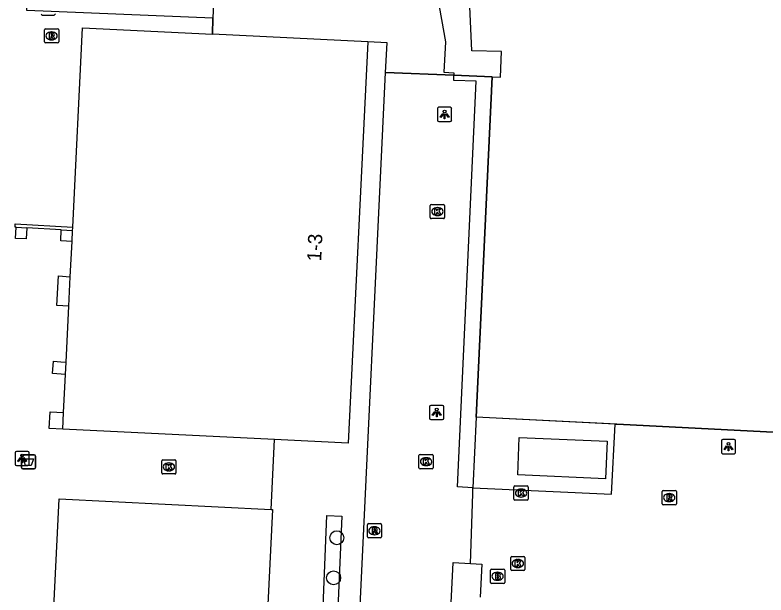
# Model space of a CAD drawing. Extents: x 161761 to 162722, y 384793 to 385405.
# Drawn here: x 162373.4 to 162426.2, y 385061.7 to 385102.4 of the extents above; entities that cross this region are included whole.
import ezdxf

# ---------------------------------------------------------------- set-up
doc = ezdxf.new("R2010")
doc.units = 0
for name, color, linetype in [('IMGEO_Afvalbak', 7, 'Continuous'), ('IMGEO_Boom', 7, 'Continuous'), ('IMGEO_Brandkraan', 7, 'Continuous'), ('IMGEO_Groenvoorziening', 7, 'Continuous'), ('IMGEO_Haag', 7, 'Continuous'), ('IMGEO_Hek', 7, 'Continuous'), ('IMGEO_Kolk', 7, 'Continuous'), ('IMGEO_Lichtpunt', 7, 'Continuous'), ('IMGEO_Loofbos', 7, 'Continuous'), ('IMGEO_Pand', 7, 'Continuous'), ('IMGEO_Pand_nummerreeks', 7, 'Continuous'), ('IMGEO_Rioolput', 7, 'Continuous'), ('IMGEO_Voetpad_open', 7, 'Continuous')]:
    doc.layers.add(name, color=color, linetype=linetype)

msp = doc.modelspace()

# ---------------------------------------------------------------- linework, layer by layer
at = {"layer": 'IMGEO_Afvalbak'}
for p, q in [((162373.853, 385070.657), (162373.853, 385071.457)), ((162373.853, 385071.457), (162373.853, 385070.657)), ((162373.953, 385071.557), (162374.743, 385071.557)), ((162374.743, 385071.557), (162373.953, 385071.557)), ((162374.843, 385071.457), (162374.843, 385070.657)), ((162374.843, 385070.657), (162374.843, 385071.457)), ((162374.743, 385070.557), (162373.953, 385070.557)), ((162373.953, 385070.557), (162374.743, 385070.557))]:
    msp.add_line(p, q, dxfattribs=at)
msp.add_lwpolyline([(162373.996, 385071.271), (162374.7, 385071.271), (162374.551, 385070.801), (162374.145, 385070.801), (162373.996, 385071.271)], dxfattribs=at)
for centre, start, end in [((162373.953, 385071.457), 90, 180), ((162373.953, 385071.457), 90, 180), ((162374.743, 385071.457), 0, 90), ((162374.743, 385071.457), 360, 90), ((162373.953, 385070.657), 180, 270), ((162373.953, 385070.657), 180, 270), ((162374.743, 385070.657), 270, 0), ((162374.743, 385070.657), 270, 0)]:
    msp.add_arc(centre, 0.1, start, end, dxfattribs=at)
at = {"layer": 'IMGEO_Boom'}
for centre in [(162396.02, 385065.722), (162395.798, 385062.901)]:
    msp.add_circle(centre, 0.489, dxfattribs=at)
at = {"layer": 'IMGEO_Brandkraan'}
for p, q in [((162406.822, 385062.587), (162406.822, 385063.439)), ((162406.897, 385063.513), (162407.749, 385063.513)), ((162407.31, 385063.293), (162407.335, 385063.293)), ((162407.823, 385063.439), (162407.823, 385062.587)), ((162407.333, 385062.733), (162407.308, 385062.733)), ((162407.749, 385062.513), (162406.897, 385062.513))]:
    msp.add_line(p, q, dxfattribs=at)
for points in [[(162406.822, 385062.587), (162406.822, 385063.439)], [(162406.897, 385063.513), (162407.749, 385063.513)], [(162407.823, 385063.439), (162407.823, 385062.587)], [(162407.17, 385063.213), (162407.17, 385062.813), (162407.383, 385062.813)], [(162407.401, 385063.213), (162407.17, 385063.213)], [(162407.349, 385063.132), (162407.295, 385063.132), (162407.295, 385063.056)], [(162407.295, 385063.056), (162407.348, 385063.056)], [(162407.357, 385062.98), (162407.295, 385062.98), (162407.295, 385062.899)], [(162407.295, 385062.899), (162407.357, 385062.899)], [(162407.749, 385062.513), (162406.897, 385062.513)]]:
    msp.add_lwpolyline(points, dxfattribs=at)
for centre, radius, start, end in [((162406.899, 385063.437), 0.0765, 91.552, 178.448), ((162406.899, 385063.437), 0.0765, 91.552, 178.448), ((162407.747, 385063.437), 0.0765, 1.552, 88.448), ((162407.747, 385063.437), 0.0765, 1.552, 88.448), ((162407.35, 385063.094), 0.0379, 267.8285, 90.9355), ((162407.358, 385062.939), 0.0404, 269.8759, 90.5077), ((162407.389, 385063.064), 0.251, 268.6676, 293.5347), ((162407.405, 385063.068), 0.145, 59.4692, 91.5367), ((162407.43, 385063.115), 0.0922, 285.5137, 58.1501), ((162407.435, 385062.923), 0.105, 301.3115, 78.989), ((162406.899, 385062.589), 0.0765, 181.552, 268.448), ((162406.899, 385062.589), 0.0765, 181.552, 268.448), ((162407.747, 385062.589), 0.0765, 271.552, 358.448), ((162407.747, 385062.589), 0.0765, 271.552, 358.448)]:
    msp.add_arc(centre, radius, start, end, dxfattribs=at)
for centre, major_axis, ratio, start_param, end_param in [((162407.309, 385063.013), (-0.387, 0.002), 0.722429, 4.712389, 7.853982), ((162407.334, 385063.013), (-0.39, 0.002), 0.717154, 1.570796, 4.712389)]:
    msp.add_ellipse(centre, major_axis=major_axis, ratio=ratio, start_param=start_param, end_param=end_param, dxfattribs=at)
at = {"layer": 'IMGEO_Groenvoorziening'}
for points in [[(162373.496, 385087.535), (162374.232, 385087.489)], [(162376.647, 385087.355), (162377.453, 385087.31)]]:
    msp.add_lwpolyline(points, dxfattribs=at)
at = {"layer": 'IMGEO_Haag'}
for points in [[(162406.946, 385098.102), (162407.536, 385098.075), (162407.59, 385099.872), (162405.506, 385099.92), (162405.19, 385107.198), (162407.287, 385109.447), (162408.471, 385113.399), (162408.538, 385116.438), (162406.588, 385116.444)], [(162404.247, 385098.213), (162406.946, 385098.102)], [(162406.946, 385098.102), (162405.822, 385074.201)], [(162405.414, 385063.918), (162406.21, 385063.87), (162406.102, 385061.54)]]:
    msp.add_lwpolyline(points, dxfattribs=at)
at = {"layer": 'IMGEO_Hek'}
for points in [[(162387.301, 385102.223), (162387.283, 385101.087)], [(162404.247, 385098.213), (162399.452, 385098.409)], [(162406.946, 385098.102), (162404.247, 385098.213)], [(162405.822, 385074.201), (162406.946, 385098.102)], [(162405.822, 385074.201), (162405.588, 385069.236)], [(162416.171, 385073.671), (162405.822, 385074.201)], [(162438.563, 385072.523), (162416.171, 385073.671)], [(162391.403, 385067.713), (162391.641, 385072.611)]]:
    msp.add_lwpolyline(points, dxfattribs=at)
at = {"layer": 'IMGEO_Kolk'}
for p, q in [((162402.668, 385089.134), (162403.52, 385089.134)), ((162402.593, 385088.208), (162402.593, 385089.06)), ((162403.081, 385088.914), (162403.106, 385088.914)), ((162403.594, 385089.06), (162403.594, 385088.208)), ((162403.52, 385088.134), (162402.668, 385088.134)), ((162403.104, 385088.354), (162403.079, 385088.354)), ((162383.794, 385071.2), (162384.646, 385071.2)), ((162401.799, 385070.64), (162401.799, 385071.492)), ((162401.874, 385071.566), (162402.726, 385071.566)), ((162402.287, 385071.346), (162402.312, 385071.346)), ((162402.8, 385071.492), (162402.8, 385070.64)), ((162383.719, 385070.274), (162383.719, 385071.126)), ((162384.207, 385070.98), (162384.232, 385070.98)), ((162384.72, 385071.126), (162384.72, 385070.274)), ((162402.31, 385070.786), (162402.285, 385070.786)), ((162384.646, 385070.2), (162383.794, 385070.2)), ((162384.23, 385070.42), (162384.205, 385070.42)), ((162402.726, 385070.566), (162401.874, 385070.566)), ((162408.471, 385068.432), (162408.471, 385069.284)), ((162408.546, 385069.358), (162409.398, 385069.358)), ((162408.959, 385069.138), (162408.984, 385069.138)), ((162409.472, 385069.284), (162409.472, 385068.432)), ((162408.982, 385068.578), (162408.957, 385068.578)), ((162409.398, 385068.358), (162408.546, 385068.358)), ((162408.245, 385063.487), (162408.245, 385064.339)), ((162408.32, 385064.413), (162409.172, 385064.413)), ((162409.246, 385064.339), (162409.246, 385063.487)), ((162408.733, 385064.193), (162408.758, 385064.193)), ((162409.172, 385063.413), (162408.32, 385063.413)), ((162408.756, 385063.633), (162408.731, 385063.633))]:
    msp.add_line(p, q, dxfattribs=at)
for points in [[(162402.668, 385089.134), (162403.52, 385089.134)], [(162402.593, 385088.208), (162402.593, 385089.06)], [(162402.914, 385088.834), (162403.037, 385088.834), (162403.037, 385088.683), (162403.167, 385088.834), (162403.331, 385088.834), (162403.185, 385088.683), (162403.338, 385088.434), (162403.186, 385088.434), (162403.101, 385088.598), (162403.037, 385088.531), (162403.037, 385088.434), (162402.914, 385088.434), (162402.914, 385088.834)], [(162403.594, 385089.06), (162403.594, 385088.208)], [(162403.52, 385088.134), (162402.668, 385088.134)], [(162383.794, 385071.2), (162384.646, 385071.2)], [(162401.799, 385070.64), (162401.799, 385071.492)], [(162401.874, 385071.566), (162402.726, 385071.566)], [(162402.12, 385071.266), (162402.243, 385071.266), (162402.243, 385071.115), (162402.373, 385071.266), (162402.537, 385071.266), (162402.391, 385071.115), (162402.544, 385070.866), (162402.392, 385070.866), (162402.307, 385071.03), (162402.243, 385070.963), (162402.243, 385070.866), (162402.12, 385070.866), (162402.12, 385071.266)], [(162402.8, 385071.492), (162402.8, 385070.64)], [(162383.719, 385070.274), (162383.719, 385071.126)], [(162384.04, 385070.9), (162384.163, 385070.9), (162384.163, 385070.749), (162384.293, 385070.9), (162384.457, 385070.9), (162384.311, 385070.749), (162384.464, 385070.5), (162384.312, 385070.5), (162384.227, 385070.664), (162384.163, 385070.597), (162384.163, 385070.5), (162384.04, 385070.5), (162384.04, 385070.9)], [(162384.72, 385071.126), (162384.72, 385070.274)], [(162384.646, 385070.2), (162383.794, 385070.2)], [(162402.726, 385070.566), (162401.874, 385070.566)], [(162408.471, 385068.432), (162408.471, 385069.284)], [(162408.546, 385069.358), (162409.398, 385069.358)], [(162408.792, 385069.058), (162408.915, 385069.058), (162408.915, 385068.907), (162409.045, 385069.058), (162409.209, 385069.058), (162409.063, 385068.907), (162409.216, 385068.658), (162409.064, 385068.658), (162408.979, 385068.822), (162408.915, 385068.755), (162408.915, 385068.658), (162408.792, 385068.658), (162408.792, 385069.058)], [(162409.472, 385069.284), (162409.472, 385068.432)], [(162409.398, 385068.358), (162408.546, 385068.358)], [(162408.245, 385063.487), (162408.245, 385064.339)], [(162408.32, 385064.413), (162409.172, 385064.413)], [(162409.246, 385064.339), (162409.246, 385063.487)], [(162408.566, 385064.113), (162408.689, 385064.113), (162408.689, 385063.962), (162408.819, 385064.113), (162408.983, 385064.113), (162408.837, 385063.962), (162408.99, 385063.713), (162408.838, 385063.713), (162408.753, 385063.877), (162408.689, 385063.81), (162408.689, 385063.713), (162408.566, 385063.713), (162408.566, 385064.113)], [(162409.172, 385063.413), (162408.32, 385063.413)]]:
    msp.add_lwpolyline(points, dxfattribs=at)
for centre, start, end in [((162402.67, 385089.058), 91.552, 178.448), ((162402.67, 385089.058), 91.552, 178.448), ((162403.518, 385089.058), 1.552, 88.448), ((162403.518, 385089.058), 1.552, 88.448), ((162402.67, 385088.21), 181.552, 268.448), ((162402.67, 385088.21), 181.552, 268.448), ((162403.518, 385088.21), 271.552, 358.448), ((162403.518, 385088.21), 271.552, 358.448), ((162383.796, 385071.124), 91.552, 178.448), ((162383.796, 385071.124), 91.552, 178.448), ((162384.644, 385071.124), 1.552, 88.448), ((162384.644, 385071.124), 1.552, 88.448), ((162401.876, 385071.49), 91.552, 178.448), ((162401.876, 385071.49), 91.552, 178.448), ((162402.724, 385071.49), 1.552, 88.448), ((162402.724, 385071.49), 1.552, 88.448), ((162401.876, 385070.642), 181.552, 268.448), ((162401.876, 385070.642), 181.552, 268.448), ((162402.724, 385070.642), 271.552, 358.448), ((162402.724, 385070.642), 271.552, 358.448), ((162383.796, 385070.276), 181.552, 268.448), ((162383.796, 385070.276), 181.552, 268.448), ((162384.644, 385070.276), 271.552, 358.448), ((162384.644, 385070.276), 271.552, 358.448), ((162408.548, 385069.282), 91.552, 178.448), ((162408.548, 385069.282), 91.552, 178.448), ((162409.396, 385069.282), 1.552, 88.448), ((162409.396, 385069.282), 1.552, 88.448), ((162408.548, 385068.434), 181.552, 268.448), ((162408.548, 385068.434), 181.552, 268.448), ((162409.396, 385068.434), 271.552, 358.448), ((162409.396, 385068.434), 271.552, 358.448), ((162408.322, 385064.337), 91.552, 178.448), ((162408.322, 385064.337), 91.552, 178.448), ((162409.17, 385064.337), 1.552, 88.448), ((162409.17, 385064.337), 1.552, 88.448), ((162408.322, 385063.489), 181.552, 268.448), ((162408.322, 385063.489), 181.552, 268.448), ((162409.17, 385063.489), 271.552, 358.448), ((162409.17, 385063.489), 271.552, 358.448)]:
    msp.add_arc(centre, 0.0765, start, end, dxfattribs=at)
for centre, major_axis, ratio, start_param, end_param in [((162403.08, 385088.634), (-0.387, 0.002), 0.722429, 4.712389, 7.853982), ((162403.105, 385088.634), (-0.39, 0.002), 0.717154, 1.570796, 4.712389), ((162402.286, 385071.066), (-0.387, 0.002), 0.722429, 4.712389, 7.853982), ((162402.311, 385071.066), (-0.39, 0.002), 0.717154, 1.570796, 4.712389), ((162384.206, 385070.7), (-0.387, 0.002), 0.722429, 4.712389, 7.853982), ((162384.231, 385070.7), (-0.39, 0.002), 0.717154, 1.570796, 4.712389), ((162408.958, 385068.858), (-0.387, 0.002), 0.722429, 4.712389, 7.853982), ((162408.983, 385068.858), (-0.39, 0.002), 0.717154, 1.570796, 4.712389), ((162408.732, 385063.913), (-0.387, 0.002), 0.722429, 4.712389, 7.853982), ((162408.757, 385063.913), (-0.39, 0.002), 0.717154, 1.570796, 4.712389)]:
    msp.add_ellipse(centre, major_axis=major_axis, ratio=ratio, start_param=start_param, end_param=end_param, dxfattribs=at)
at = {"layer": 'IMGEO_Lichtpunt'}
for p, q in [((162375.341, 385102.437), (162376.149, 385102.437)), ((162375.341, 385102.437), (162376.149, 385102.437)), ((162404.001, 385095.955), (162403.193, 385095.955)), ((162404.001, 385095.955), (162403.193, 385095.955)), ((162403.099, 385095.86), (162403.099, 385095.053)), ((162403.099, 385095.86), (162403.099, 385095.053)), ((162404.095, 385095.053), (162404.095, 385095.86)), ((162404.095, 385095.053), (162404.095, 385095.86)), ((162403.193, 385094.959), (162404.001, 385094.959)), ((162403.193, 385094.959), (162404.001, 385094.959)), ((162402.544, 385074.924), (162402.544, 385074.117)), ((162402.544, 385074.924), (162402.544, 385074.117)), ((162403.446, 385075.019), (162402.638, 385075.019)), ((162403.446, 385075.019), (162402.638, 385075.019)), ((162403.54, 385074.117), (162403.54, 385074.924)), ((162403.54, 385074.117), (162403.54, 385074.924)), ((162402.638, 385074.023), (162403.446, 385074.023)), ((162402.638, 385074.023), (162403.446, 385074.023)), ((162423.049, 385072.525), (162423.049, 385071.718)), ((162423.049, 385072.525), (162423.049, 385071.718)), ((162423.951, 385072.62), (162423.143, 385072.62)), ((162423.951, 385072.62), (162423.143, 385072.62)), ((162424.045, 385071.718), (162424.045, 385072.525)), ((162424.045, 385071.718), (162424.045, 385072.525)), ((162373.408, 385071.69), (162373.408, 385070.883)), ((162373.408, 385071.69), (162373.408, 385070.883)), ((162374.31, 385071.785), (162373.502, 385071.785)), ((162374.31, 385071.785), (162373.502, 385071.785)), ((162374.404, 385070.883), (162374.404, 385071.69)), ((162374.404, 385070.883), (162374.404, 385071.69)), ((162423.143, 385071.624), (162423.951, 385071.624)), ((162423.143, 385071.624), (162423.951, 385071.624)), ((162373.502, 385070.789), (162374.31, 385070.789)), ((162373.502, 385070.789), (162374.31, 385070.789))]:
    msp.add_line(p, q, dxfattribs=at)
for points in [[(162403.473, 385095.524), (162403.512, 385095.496), (162403.324, 385095.234), (162403.286, 385095.261), (162403.473, 385095.524)], [(162403.575, 385095.476), (162403.622, 385095.476), (162403.622, 385095.154), (162403.575, 385095.154), (162403.575, 385095.476)], [(162403.685, 385095.496), (162403.723, 385095.523), (162403.91, 385095.261), (162403.871, 385095.233), (162403.685, 385095.496)], [(162402.918, 385074.588), (162402.957, 385074.56), (162402.769, 385074.298), (162402.731, 385074.325), (162402.918, 385074.588)], [(162403.02, 385074.54), (162403.067, 385074.54), (162403.067, 385074.218), (162403.02, 385074.218), (162403.02, 385074.54)], [(162403.13, 385074.56), (162403.168, 385074.587), (162403.355, 385074.325), (162403.316, 385074.297), (162403.13, 385074.56)], [(162423.423, 385072.189), (162423.462, 385072.161), (162423.274, 385071.899), (162423.236, 385071.926), (162423.423, 385072.189)], [(162423.525, 385072.141), (162423.572, 385072.141), (162423.572, 385071.819), (162423.525, 385071.819), (162423.525, 385072.141)], [(162423.635, 385072.161), (162423.673, 385072.188), (162423.86, 385071.926), (162423.821, 385071.898), (162423.635, 385072.161)], [(162373.782, 385071.354), (162373.821, 385071.326), (162373.633, 385071.064), (162373.595, 385071.091), (162373.782, 385071.354)], [(162373.884, 385071.306), (162373.931, 385071.306), (162373.931, 385070.984), (162373.884, 385070.984), (162373.884, 385071.306)], [(162373.994, 385071.326), (162374.032, 385071.353), (162374.219, 385071.091), (162374.18, 385071.063), (162373.994, 385071.326)]]:
    msp.add_lwpolyline(points, dxfattribs=at)
for centre in [(162403.598, 385095.658), (162403.043, 385074.722), (162423.548, 385072.323), (162373.907, 385071.488)]:
    msp.add_circle(centre, 0.0994, dxfattribs=at)
for centre, start, end in [((162375.341, 385102.531), 180, 270), ((162375.341, 385102.531), 180, 270), ((162376.149, 385102.531), 270, 0), ((162376.149, 385102.531), 270, 360), ((162403.193, 385095.86), 90, 180), ((162403.193, 385095.86), 90, 180), ((162404.001, 385095.86), 0, 90), ((162404.001, 385095.86), 0, 90), ((162403.193, 385095.053), 180, 270), ((162403.193, 385095.053), 180, 270), ((162404.001, 385095.053), 270, 0), ((162404.001, 385095.053), 270, 360), ((162402.638, 385074.924), 90, 180), ((162402.638, 385074.924), 90, 180), ((162403.446, 385074.924), 0, 90), ((162403.446, 385074.924), 0, 90), ((162402.638, 385074.117), 180, 270), ((162402.638, 385074.117), 180, 270), ((162403.446, 385074.117), 270, 0), ((162403.446, 385074.117), 270, 360), ((162423.143, 385072.525), 90, 180), ((162423.143, 385072.525), 90, 180), ((162423.951, 385072.525), 0, 90), ((162423.951, 385072.525), 0, 90), ((162373.502, 385071.69), 90, 180), ((162373.502, 385071.69), 90, 180), ((162374.31, 385071.69), 0, 90), ((162374.31, 385071.69), 0, 90), ((162423.143, 385071.718), 180, 270), ((162423.143, 385071.718), 180, 270), ((162423.951, 385071.718), 270, 0), ((162423.951, 385071.718), 270, 360), ((162373.502, 385070.883), 180, 270), ((162373.502, 385070.883), 180, 270), ((162374.31, 385070.883), 270, 0), ((162374.31, 385070.883), 270, 360)]:
    msp.add_arc(centre, 0.0946, start, end, dxfattribs=at)
at = {"layer": 'IMGEO_Loofbos'}
msp.add_lwpolyline([(162415.586, 385073.701), (162416.171, 385073.671), (162438.563, 385072.523)], dxfattribs=at)
at = {"layer": 'IMGEO_Pand'}
for points in [[(162377.464, 385087.529), (162378.156, 385101.538), (162387.283, 385101.087)], [(162398.207, 385100.548), (162387.283, 385101.087)], [(162398.207, 385100.548), (162396.815, 385072.356), (162391.641, 385072.611), (162376.764, 385073.346)], [(162377.453, 385087.31), (162377.462, 385087.485), (162377.464, 385087.529)], [(162377.415, 385086.541), (162377.453, 385087.31)], [(162377.292, 385084.054), (162377.415, 385086.541)], [(162377.19, 385081.987), (162377.292, 385084.054)], [(162376.996, 385078.06), (162377.19, 385081.987)], [(162376.953, 385077.182), (162376.996, 385078.06)], [(162376.822, 385074.53), (162376.953, 385077.182)], [(162376.764, 385073.346), (162376.822, 385074.53)], [(162408.735, 385070.132), (162408.849, 385072.765), (162415.023, 385072.498), (162414.91, 385069.866), (162408.735, 385070.132)], [(162376.514, 385068.444), (162391.403, 385067.713), (162391.509, 385067.708), (162389.358, 385023.855), (162374.363, 385024.591), (162376.514, 385068.444)]]:
    msp.add_lwpolyline(points, dxfattribs=at)
at = {"layer": 'IMGEO_Rioolput'}
for p, q in [((162375.475, 385100.548), (162375.475, 385101.4)), ((162375.55, 385101.474), (162376.402, 385101.474)), ((162375.963, 385101.254), (162375.988, 385101.254)), ((162376.476, 385101.4), (162376.476, 385100.548)), ((162376.402, 385100.474), (162375.55, 385100.474)), ((162375.986, 385100.694), (162375.961, 385100.694)), ((162418.963, 385069.039), (162419.815, 385069.039)), ((162418.888, 385068.113), (162418.888, 385068.965)), ((162419.376, 385068.819), (162419.401, 385068.819)), ((162419.889, 385068.965), (162419.889, 385068.113)), ((162419.815, 385068.039), (162418.963, 385068.039)), ((162419.399, 385068.259), (162419.374, 385068.259)), ((162398.169, 385065.785), (162398.169, 385066.637)), ((162398.244, 385066.711), (162399.096, 385066.711)), ((162398.657, 385066.491), (162398.682, 385066.491)), ((162399.17, 385066.637), (162399.17, 385065.785)), ((162398.68, 385065.931), (162398.655, 385065.931)), ((162399.096, 385065.711), (162398.244, 385065.711))]:
    msp.add_line(p, q, dxfattribs=at)
for points in [[(162375.475, 385100.548), (162375.475, 385101.4)], [(162375.55, 385101.474), (162376.402, 385101.474)], [(162376.476, 385101.4), (162376.476, 385100.548)], [(162376.064, 385101.172), (162375.812, 385101.174), (162375.812, 385100.774)], [(162375.812, 385100.774), (162375.936, 385100.774), (162375.936, 385100.936), (162375.947, 385100.936)], [(162375.99, 385101.093), (162375.936, 385101.093), (162375.936, 385101.012)], [(162375.936, 385101.012), (162375.988, 385101.012)], [(162375.994, 385100.907), (162376.065, 385100.774), (162376.205, 385100.774), (162376.14, 385100.9)], [(162376.402, 385100.474), (162375.55, 385100.474)], [(162418.963, 385069.039), (162419.815, 385069.039)], [(162418.888, 385068.113), (162418.888, 385068.965)], [(162419.477, 385068.737), (162419.225, 385068.739), (162419.225, 385068.339)], [(162419.403, 385068.658), (162419.349, 385068.658), (162419.349, 385068.577)], [(162419.349, 385068.577), (162419.401, 385068.577)], [(162419.889, 385068.965), (162419.889, 385068.113)], [(162419.815, 385068.039), (162418.963, 385068.039)], [(162419.225, 385068.339), (162419.349, 385068.339), (162419.349, 385068.501), (162419.36, 385068.501)], [(162419.407, 385068.472), (162419.478, 385068.339), (162419.618, 385068.339), (162419.553, 385068.465)], [(162398.169, 385065.785), (162398.169, 385066.637)], [(162398.244, 385066.711), (162399.096, 385066.711)], [(162398.758, 385066.409), (162398.506, 385066.411), (162398.506, 385066.011)], [(162399.17, 385066.637), (162399.17, 385065.785)], [(162398.506, 385066.011), (162398.63, 385066.011), (162398.63, 385066.173), (162398.641, 385066.173)], [(162398.684, 385066.33), (162398.63, 385066.33), (162398.63, 385066.249)], [(162398.63, 385066.249), (162398.682, 385066.249)], [(162398.688, 385066.144), (162398.759, 385066.011), (162398.899, 385066.011), (162398.834, 385066.137)], [(162399.096, 385065.711), (162398.244, 385065.711)]]:
    msp.add_lwpolyline(points, dxfattribs=at)
for centre, radius, start, end in [((162375.552, 385101.398), 0.0765, 91.552, 178.448), ((162375.552, 385101.398), 0.0765, 91.552, 178.448), ((162376.4, 385101.398), 0.0765, 1.552, 88.448), ((162376.4, 385101.398), 0.0765, 1.552, 88.448), ((162375.946, 385100.883), 0.0533, 26.0293, 88.6989), ((162375.972, 385101.201), 0.19, 274.7715, 282.9687), ((162375.996, 385100.997), 0.0964, 77.0061, 93.1865), ((162376.01, 385101.054), 0.0378, 276.6634, 79.6772), ((162376.063, 385101.062), 0.109, 350.3612, 89.416), ((162376.061, 385101.062), 0.112, 277.5842, 350.9817), ((162376.045, 385100.847), 0.108, 29.5134, 73.7905), ((162375.552, 385100.55), 0.0765, 181.552, 268.448), ((162375.552, 385100.55), 0.0765, 181.552, 268.448), ((162376.4, 385100.55), 0.0765, 271.552, 358.448), ((162376.4, 385100.55), 0.0765, 271.552, 358.448), ((162418.965, 385068.963), 0.0765, 91.552, 178.448), ((162418.965, 385068.963), 0.0765, 91.552, 178.448), ((162419.813, 385068.963), 0.0765, 1.552, 88.448), ((162419.813, 385068.963), 0.0765, 1.552, 88.448), ((162419.385, 385068.766), 0.19, 274.7715, 282.9687), ((162419.409, 385068.562), 0.0964, 77.0061, 93.1865), ((162419.423, 385068.619), 0.0378, 276.6634, 79.6772), ((162419.476, 385068.627), 0.109, 350.3612, 89.416), ((162419.474, 385068.627), 0.112, 277.5842, 350.9817), ((162419.458, 385068.412), 0.108, 29.5134, 73.7905), ((162418.965, 385068.115), 0.0765, 181.552, 268.448), ((162418.965, 385068.115), 0.0765, 181.552, 268.448), ((162419.359, 385068.448), 0.0533, 26.0293, 88.6989), ((162419.813, 385068.115), 0.0765, 271.552, 358.448), ((162419.813, 385068.115), 0.0765, 271.552, 358.448), ((162398.246, 385066.635), 0.0765, 91.552, 178.448), ((162398.246, 385066.635), 0.0765, 91.552, 178.448), ((162398.757, 385066.299), 0.109, 350.3612, 89.416), ((162399.094, 385066.635), 0.0765, 1.552, 88.448), ((162399.094, 385066.635), 0.0765, 1.552, 88.448), ((162398.64, 385066.12), 0.0533, 26.0293, 88.6989), ((162398.666, 385066.438), 0.19, 274.7715, 282.9687), ((162398.69, 385066.234), 0.0964, 77.0061, 93.1865), ((162398.704, 385066.291), 0.0378, 276.6634, 79.6772), ((162398.755, 385066.299), 0.112, 277.5842, 350.9817), ((162398.739, 385066.084), 0.108, 29.5134, 73.7905), ((162398.246, 385065.787), 0.0765, 181.552, 268.448), ((162398.246, 385065.787), 0.0765, 181.552, 268.448), ((162399.094, 385065.787), 0.0765, 271.552, 358.448), ((162399.094, 385065.787), 0.0765, 271.552, 358.448)]:
    msp.add_arc(centre, radius, start, end, dxfattribs=at)
for centre, major_axis, ratio, start_param, end_param in [((162375.962, 385100.974), (-0.387, 0.002), 0.722429, 4.712389, 7.853982), ((162375.987, 385100.974), (-0.39, 0.002), 0.717154, 1.570796, 4.712389), ((162419.375, 385068.539), (-0.387, 0.002), 0.722429, 4.712389, 7.853982), ((162419.4, 385068.539), (-0.39, 0.002), 0.717154, 1.570796, 4.712389), ((162398.656, 385066.211), (-0.387, 0.002), 0.722429, 4.712389, 7.853982), ((162398.681, 385066.211), (-0.39, 0.002), 0.717154, 1.570796, 4.712389)]:
    msp.add_ellipse(centre, major_axis=major_axis, ratio=ratio, start_param=start_param, end_param=end_param, dxfattribs=at)
at = {"layer": 'IMGEO_Voetpad_open'}
for points in [[(162387.301, 385102.223), (162374.244, 385102.765), (162374.402, 385106.118), (162378.278, 385110.648)], [(162387.725, 385110.167), (162387.405, 385104.322), (162387.301, 385102.223)], [(162402.944, 385104.629), (162403.666, 385100.554), (162403.541, 385098.416), (162404.25, 385098.383), (162404.247, 385098.213)], [(162387.283, 385101.087), (162387.301, 385102.223)], [(162399.452, 385098.409), (162399.551, 385100.482), (162398.207, 385100.548)], [(162395.555, 385016.551), (162399.452, 385098.409)], [(162399.452, 385098.409), (162404.247, 385098.213)], [(162405.588, 385069.236), (162404.495, 385069.287), (162405.806, 385097.791), (162404.241, 385097.842), (162404.247, 385098.213)], [(162373.496, 385087.535), (162373.407, 385087.54), (162373.415, 385087.759), (162377.464, 385087.529)], [(162374.232, 385087.489), (162374.187, 385086.711), (162373.435, 385086.739), (162373.496, 385087.535)], [(162376.647, 385087.355), (162374.232, 385087.489)], [(162377.415, 385086.541), (162376.616, 385086.583), (162376.647, 385087.355)], [(162377.19, 385081.987), (162376.338, 385082.032), (162376.465, 385084.124), (162377.292, 385084.054)], [(162376.953, 385077.182), (162376.047, 385077.257), (162376.1, 385078.123), (162376.628, 385078.086), (162376.996, 385078.06)], [(162376.764, 385073.346), (162375.811, 385073.388), (162375.882, 385074.555), (162376.822, 385074.53)], [(162405.822, 385074.201), (162405.588, 385069.236)], [(162415.586, 385073.701), (162405.822, 385074.201)], [(162405.588, 385069.236), (162415.334, 385068.786), (162415.586, 385073.701)], [(162405.414, 385063.918), (162405.573, 385068.801), (162405.588, 385069.236)], [(162395.326, 385067.279), (162396.368, 385067.236), (162396.033, 385059.11), (162394.991, 385059.153), (162395.326, 385067.279)], [(162402.942, 385038.647), (162404.199, 385063.991), (162405.414, 385063.918)]]:
    msp.add_lwpolyline(points, dxfattribs=at)

# ---------------------------------------------------------------- texts
at = {"layer": 'IMGEO_Pand_nummerreeks'}
msp.add_text('1-3', height=1, rotation=87.1755, dxfattribs=at).set_placement((162394.922, 385085.119))

doc.saveas('drawing.dxf')
